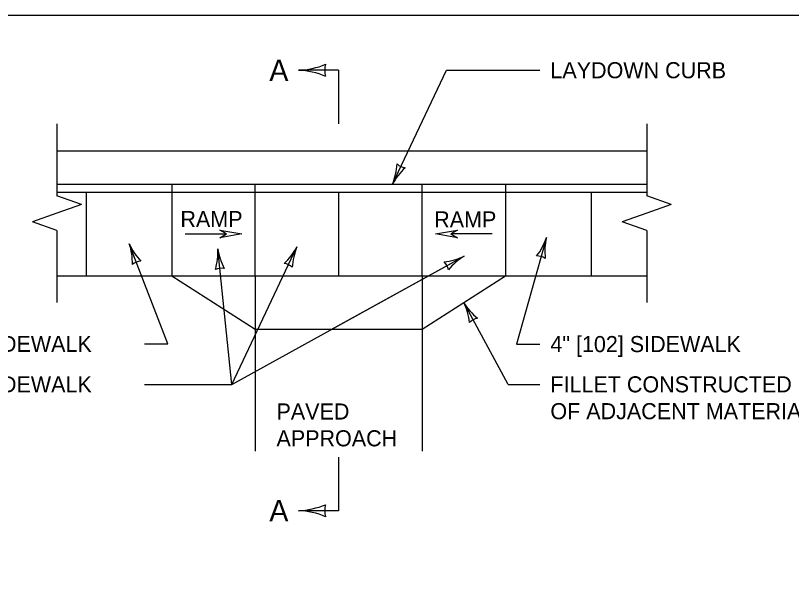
# Model space of a CAD drawing. Extents: x 49987.9 to 50021, y 49987.6 to 50011.4.
# Drawn here: x 50002.462 to 50005.356, y 50009.174 to 50011.263 of the extents above; entities that cross this region are included whole.
import ezdxf

# ---------------------------------------------------------------- set-up
doc = ezdxf.new("R2010")
doc.units = 0
for name, color, linetype in [('Level 1', 7, 'Continuous'), ('Level 2', 7, 'Continuous'), ('Level 3', 7, 'Continuous'), ('Level 4', 7, 'Continuous'), ('Level 6', 7, 'Continuous'), ('Level 7', 7, 'Continuous')]:
    doc.layers.add(name, color=color, linetype=linetype)

msp = doc.modelspace()

# ---------------------------------------------------------------- linework, layer by layer
at = {"layer": 'Level 1'}
for p, q in [((50002.6159, 50010.7584), (50004.8159, 50010.7584)), ((50002.6159, 50010.6334), (50003.3559, 50010.6334)), ((50003.0449, 50010.6334), (50003.0449, 50010.6034)), ((50003.3559, 50010.2924), (50003.3559, 50010.6334)), ((50003.9779, 50010.6334), (50004.8159, 50010.6334)), ((50003.9779, 50010.2924), (50003.9779, 50010.6334)), ((50004.2889, 50010.6334), (50004.2889, 50010.6034)), ((50002.6159, 50010.6034), (50003.3559, 50010.6034)), ((50002.7249, 50010.6034), (50002.7249, 50010.2924)), ((50003.0449, 50010.6034), (50003.0449, 50010.2924)), ((50003.3559, 50010.6034), (50003.9779, 50010.6034)), ((50003.6669, 50010.6034), (50003.6669, 50010.2924)), ((50003.9779, 50010.6034), (50004.8159, 50010.6034)), ((50004.2889, 50010.6034), (50004.2889, 50010.2924)), ((50004.6089, 50010.6034), (50004.6089, 50010.2924)), ((50002.6159, 50010.2924), (50004.8159, 50010.2924)), ((50003.0449, 50010.2924), (50003.3559, 50010.0924)), ((50003.0449, 50010.2924), (50004.2889, 50010.2924)), ((50003.3559, 50010.2924), (50003.3559, 50009.6377)), ((50003.9779, 50010.0924), (50004.2889, 50010.2924)), ((50003.9779, 50010.2924), (50003.9779, 50009.6377)), ((50003.3559, 50010.0924), (50003.9779, 50010.0924))]:
    msp.add_line(p, q, dxfattribs=at)
msp.add_lwpolyline([(50008.6146, 50011.2628), (50000.3356, 50011.2628), (50000.3356, 50000.0624), (50008.6146, 50000.0624)], close=True, dxfattribs=at)
at = {"layer": 'Level 3'}
for p, q in [((50003.8673, 50010.6334), (50004.0687, 50011.0588)), ((50004.0687, 50011.0588), (50004.4167, 50011.0588)), ((50004.4421, 50010.4346), (50004.3308, 50010.0373)), ((50003.0292, 50010.038), (50002.886, 50010.4116)), ((50003.2687, 50009.8871), (50003.5114, 50010.3996)), ((50003.2687, 50009.8871), (50003.5114, 50010.3996)), ((50003.2687, 50009.8871), (50003.2158, 50010.3928)), ((50003.2687, 50009.8871), (50004.1351, 50010.3656)), ((50003.6387, 50010.0915), (50004.1351, 50010.3656)), ((50004.2996, 50009.8871), (50004.1334, 50010.1924)), ((50002.9433, 50010.038), (50003.0292, 50010.038)), ((50004.3308, 50010.0373), (50004.4167, 50010.0373)), ((50002.9433, 50009.8871), (50003.2687, 50009.8871)), ((50004.2996, 50009.8871), (50004.4167, 50009.8871))]:
    msp.add_line(p, q, dxfattribs=at)
for centre, radius, start, end in [((50003.5016, 50011.3687), 0.3107, 272.8273, 292.0772), ((50003.6879, 50011.0584), 0.073, 162.1388, 197.8612), ((50003.5047, 50010.7622), 0.2964, 67.456, 87.6395), ((50003.6521, 50010.7226), 0.233, 337.492, 356.7419), ((50004.0642, 50010.5301), 0.2223, 132.1207, 152.3042), ((50003.9222, 50010.7493), 0.0548, 226.8035, 262.5259), ((50004.2211, 50010.5085), 0.233, 322.2701, 341.52), ((50004.6584, 50010.3835), 0.2223, 166.7078, 186.8913), ((50002.6753, 50010.3406), 0.2223, 358.4279, 18.6114), ((50003.0992, 50010.5056), 0.233, 203.7992, 223.0491), ((50003.3146, 50010.5029), 0.2223, 312.1197, 332.3032), ((50003.3146, 50010.5029), 0.2223, 312.1197, 332.3032), ((50003.7266, 50010.3104), 0.233, 157.491, 176.7409), ((50003.7266, 50010.3104), 0.233, 157.491, 176.7409), ((50002.9939, 50010.3788), 0.2223, 343.4322, 3.6158), ((50003.446, 50010.4285), 0.233, 188.8035, 208.0534), ((50004.0357, 50010.5645), 0.2223, 276.3699, 296.5534), ((50004.0357, 50010.5645), 0.2223, 276.3699, 296.5534), ((50004.2577, 50010.1674), 0.233, 121.7412, 140.9911), ((50004.2577, 50010.1674), 0.233, 121.7412, 140.9911), ((50004.4075, 50010.3111), 0.0548, 56.4861, 92.2085), ((50002.9319, 50010.2919), 0.0548, 93.1107, 128.8331), ((50003.4565, 50010.2837), 0.0548, 46.8025, 82.5249), ((50003.4565, 50010.2837), 0.0548, 46.8025, 82.5249), ((50004.0229, 50010.3036), 0.0548, 11.0527, 46.7751), ((50004.0229, 50010.3036), 0.0548, 11.0527, 46.7751), ((50003.2291, 50010.2653), 0.0548, 78.1151, 113.8374), ((50003.9339, 50010.0942), 0.2223, 6.0191, 26.2026), ((50004.3323, 50010.3138), 0.233, 211.3904, 230.6403), ((50004.1947, 50010.0798), 0.0548, 100.7019, 136.4243), ((50003.5016, 50009.7262), 0.3107, 272.8273, 292.0772), ((50003.5047, 50009.1197), 0.2964, 67.456, 87.6395), ((50003.6879, 50009.4159), 0.073, 162.1388, 197.8612)]:
    msp.add_arc(centre, radius, start, end, dxfattribs=at)
at = {"layer": 'Level 4'}
msp.add_line((50003.3559, 50010.6334), (50003.9779, 50010.6334), dxfattribs=at)
at = {"layer": 'Level 6'}
for p, q in [((50003.6669, 50011.0584), (50003.5169, 50011.0584)), ((50003.6669, 50011.0584), (50003.6669, 50010.8584)), ((50002.6159, 50010.8584), (50002.6159, 50010.5902)), ((50004.8159, 50010.8584), (50004.8159, 50010.5902)), ((50002.7073, 50010.5578), (50002.6159, 50010.5902)), ((50004.9073, 50010.5578), (50004.8159, 50010.5902)), ((50002.7073, 50010.5578), (50002.6159, 50010.5254)), ((50004.9073, 50010.5578), (50004.8159, 50010.5254)), ((50002.6159, 50010.5254), (50002.5245, 50010.493)), ((50004.8159, 50010.5254), (50004.7245, 50010.493)), ((50002.6159, 50010.4606), (50002.5245, 50010.493)), ((50004.8159, 50010.4606), (50004.7245, 50010.493)), ((50002.6159, 50010.4606), (50002.6159, 50010.1924)), ((50004.8159, 50010.4606), (50004.8159, 50010.1924)), ((50003.6669, 50009.6159), (50003.6669, 50009.4159)), ((50003.6669, 50009.4159), (50003.5169, 50009.4159))]:
    msp.add_line(p, q, dxfattribs=at)
at = {"layer": 'Level 7'}
for p, q in [((50003.0949, 50010.4479), (50003.2484, 50010.4479)), ((50004.2389, 50010.4479), (50004.0854, 50010.4479))]:
    msp.add_line(p, q, dxfattribs=at)
for points in [[(50003.2231, 50010.4625), (50003.3059, 50010.4479), (50003.2231, 50010.4332), (50003.2484, 50010.4479)], [(50004.1107, 50010.4333), (50004.0279, 50010.4479), (50004.1107, 50010.4626), (50004.0854, 50010.4479)]]:
    msp.add_lwpolyline(points, close=True, dxfattribs=at)

# ---------------------------------------------------------------- texts
at = {"layer": 'Level 2'}
for s, height, p in [('A', 0.08, (50003.4082, 50011.0184)), ('LAYDOWN CURB', 0.06, (50004.4567, 50011.0288)), ('RAMP', 0.06, (50003.0766, 50010.4737)), ('RAMP', 0.06, (50004.0233, 50010.4723)), ('4" [102] SIDEWALK', 0.06, (50002.0353, 50010.008)), ('4" [102] SIDEWALK', 0.06, (50004.4567, 50010.0073)), ('6" [152] SIDEWALK', 0.06, (50002.0353, 50009.8571)), ('FILLET CONSTRUCTED', 0.06, (50004.4567, 50009.8571)), ('PAVED', 0.06, (50003.435, 50009.7559)), ('OF ADJACENT MATERIAL', 0.06, (50004.4567, 50009.7571)), ('APPROACH', 0.06, (50003.435, 50009.6559)), ('A', 0.08, (50003.4082, 50009.3759))]:
    msp.add_text(s, height=height, dxfattribs=at).set_placement(p)

doc.saveas('drawing.dxf')
